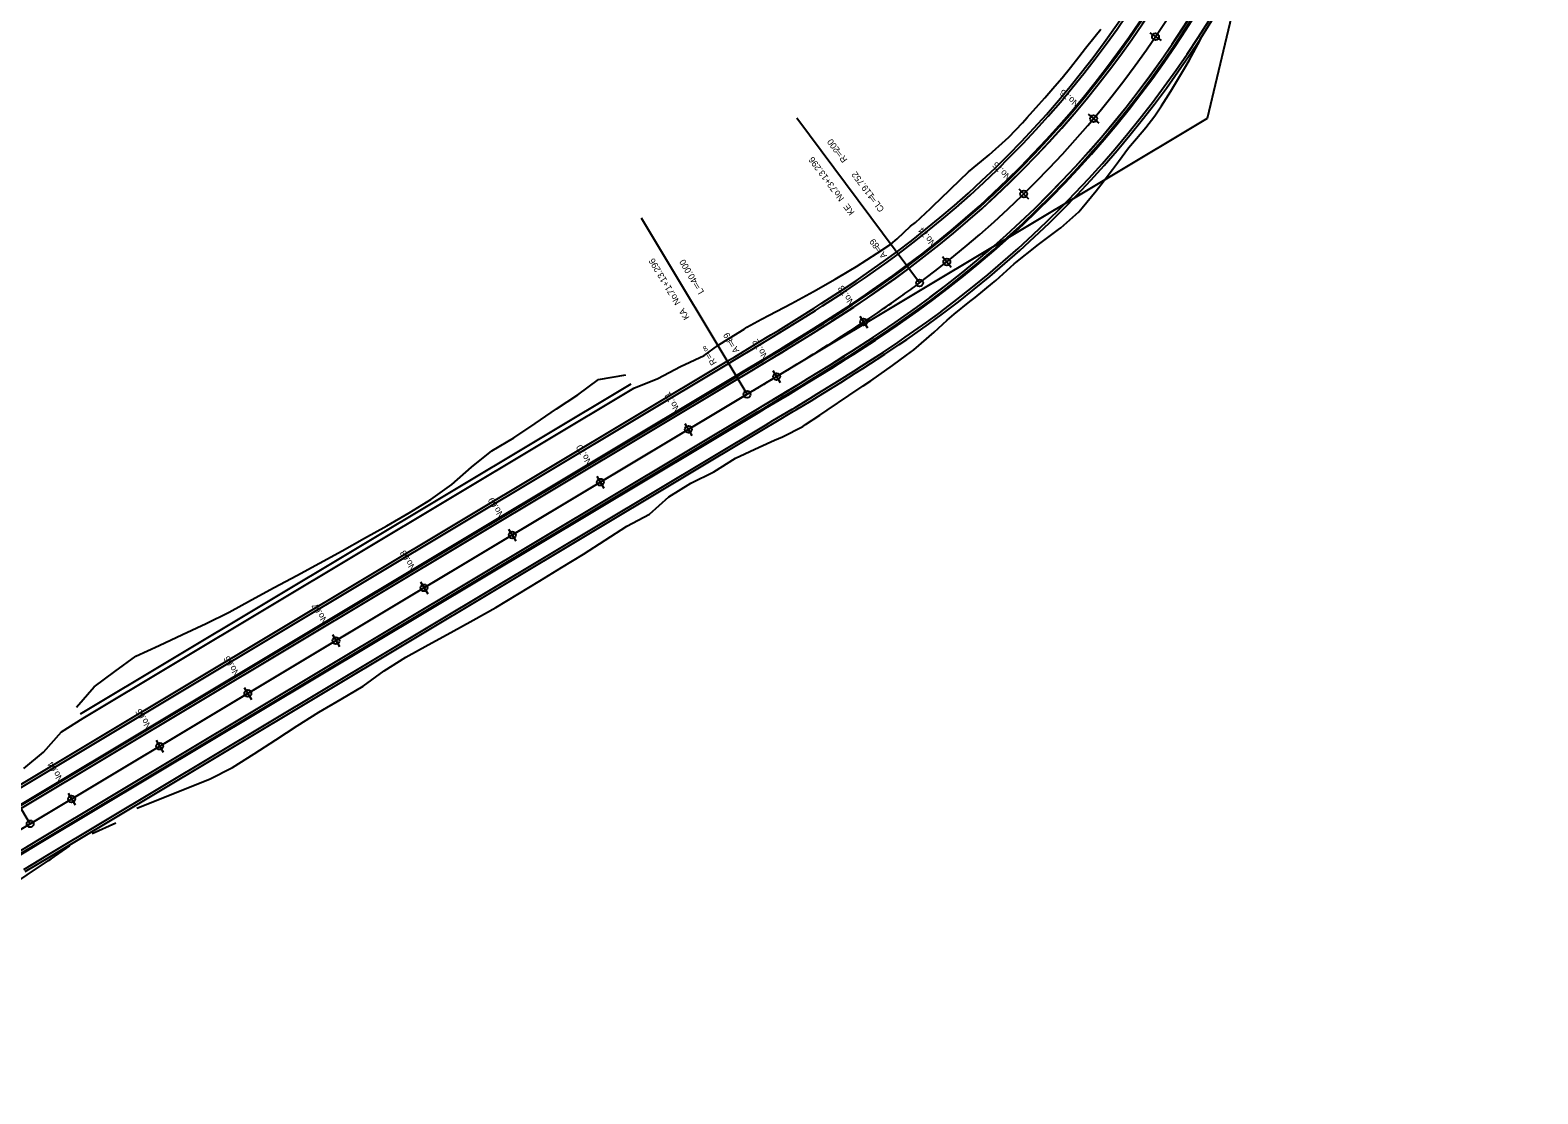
# Model space of a CAD drawing. Extents: x 46424 to 47578, y 10417 to 11548.
# Drawn here: x 47269.9 to 47563.5, y 11080.9 to 11288 of the extents above; entities that cross this region are included whole.
import ezdxf

# ---------------------------------------------------------------- set-up
doc = ezdxf.new("R2010")
doc.units = 0
for name, color, linetype in [('Default', 7, 'Continuous'), ('出典（地理院地図Vector）', 7, 'Continuous'), ('河川_人工水路(地下)（地理院地図Vector）', 7, 'Continuous'), ('現況_地形', 7, 'Continuous'), ('現況_地形_三角形', 7, 'Continuous'), ('現況_地形_三角形_頂点', 7, 'Continuous'), ('現況_地形_低い点', 7, 'Continuous'), ('現況_地形_単点標高', 7, 'Continuous'), ('現況_地形_等高線_マイナー', 7, 'Continuous'), ('等高線等深線_等高線_補助曲線通常部（地理院地図Vector）', 7, 'Continuous'), ('設計図面_測点 ラベル メジャー', 7, 'Continuous'), ('設計図面_測点 印 メジャー', 7, 'Continuous')]:
    doc.layers.add(name, color=color, linetype=linetype)

msp = doc.modelspace()

# ---------------------------------------------------------------- linework, layer by layer
at = {"layer": 'Default'}
for p, q in [((47499.18, 11270.82), (47563.47, 11542.81)), ((47489.04, 11286.7), (47489.04, 11286.7)), ((47182.22, 11080.85), (47499.18, 11270.82)), ((47443.1, 11238.76), (47419.22, 11270.84)), ((47443.1, 11238.76), (47419.22, 11270.84)), ((47476.98, 11270.75), (47476.98, 11270.75)), ((47463.39, 11256.09), (47463.39, 11256.09)), ((47409.51, 11217.07), (47388.95, 11251.38)), ((47448.41, 11242.85), (47448.41, 11242.85)), ((47443.1, 11238.76), (47443.1, 11238.76)), ((47432.21, 11231.14), (47432.21, 11231.14)), ((47415.26, 11220.53), (47415.26, 11220.53)), ((47269.95, 11133.43), (47409.51, 11217.07)), ((47409.51, 11217.07), (47409.51, 11217.07)), ((47398.11, 11210.24), (47398.11, 11210.24)), ((47380.95, 11199.96), (47380.95, 11199.96)), ((47363.8, 11189.68), (47363.8, 11189.68)), ((47346.64, 11179.39), (47346.64, 11179.39)), ((47329.49, 11169.11), (47329.49, 11169.11)), ((47269.95, 11133.43), (47249.39, 11167.74)), ((47312.33, 11158.83), (47312.33, 11158.83)), ((47295.18, 11148.55), (47295.18, 11148.55)), ((47278.02, 11138.27), (47278.02, 11138.27)), ((47269.95, 11133.43), (47269.95, 11133.43))]:
    msp.add_line(p, q, dxfattribs=at)
for centre in [(47489.04, 11286.7), (47476.98, 11270.75), (47463.39, 11256.09), (47448.41, 11242.85), (47443.1, 11238.76), (47432.21, 11231.14), (47415.26, 11220.53), (47409.51, 11217.07), (47398.11, 11210.24), (47380.95, 11199.96), (47363.8, 11189.68), (47346.64, 11179.39), (47329.49, 11169.11), (47312.33, 11158.83), (47295.18, 11148.55), (47278.02, 11138.27), (47269.95, 11133.43)]:
    msp.add_circle(centre, 0.675, dxfattribs=at)
msp.add_arc((47323.67, 11399.19), 200, 306.6653, 340.9717, dxfattribs=at)
msp.add_arc((47323.67, 11399.19), 200, 306.6653, 340.9717, dxfattribs=at)
for points in [[(47409.51, 11217.07), (47410.46, 11217.65), (47412.37, 11218.79), (47416.18, 11221.08), (47420.93, 11223.96), (47426.59, 11227.48), (47432.19, 11231.1), (47436.79, 11234.21), (47440.42, 11236.78), (47442.21, 11238.1), (47443.1, 11238.76)], [(47409.51, 11217.07), (47410.46, 11217.65), (47412.37, 11218.79), (47416.18, 11221.08), (47420.93, 11223.96), (47426.59, 11227.48), (47432.19, 11231.1), (47436.79, 11234.21), (47440.42, 11236.78), (47442.21, 11238.1), (47443.1, 11238.76)], [(47226.71, 11108.33), (47228.54, 11109.32), (47232.19, 11111.33), (47239.46, 11115.42), (47248.47, 11120.63), (47257.44, 11125.94), (47264.59, 11130.22), (47268.16, 11132.36), (47269.95, 11133.43)], [(47226.71, 11108.33), (47228.54, 11109.32), (47232.19, 11111.33), (47239.46, 11115.42), (47248.47, 11120.63), (47257.44, 11125.94), (47264.59, 11130.22), (47268.16, 11132.36), (47269.95, 11133.43)]]:
    msp.add_open_spline(points, degree=3, dxfattribs=at)
at = {"layer": '出典（地理院地図Vector）'}
for points in [[(47266.09, 11139.86), (47405.66, 11223.51), (47407.12, 11224.38), (47410.84, 11226.62), (47411.38, 11226.95), (47414.18, 11228.64), (47415.62, 11229.52), (47419.82, 11232.11), (47422.56, 11233.83), (47423.97, 11234.73), (47428.07, 11237.39), (47430.73, 11239.18), (47432.1, 11240.11), (47436.06, 11242.9), (47438.62, 11244.78)], [(47269.01, 11124.12), (47273.81, 11127), (47413.37, 11210.64), (47414.83, 11211.52), (47418.58, 11213.77), (47419.13, 11214.1), (47421.97, 11215.82), (47423.44, 11216.72), (47427.75, 11219.38), (47430.59, 11221.16), (47432.06, 11222.1), (47436.35, 11224.88), (47439.16, 11226.77), (47440.6, 11227.76), (47444.82, 11230.73), (47447.58, 11232.74)]]:
    msp.add_lwpolyline(points, dxfattribs=at)
for radius in [192.5, 207.5]:
    msp.add_arc((47323.67, 11399.19), radius, 306.6653, 340.9717, dxfattribs=at)
at = {"layer": '河川_人工水路(地下)（地理院地図Vector）'}
msp.add_line((47269.95, 11133.43), (47409.51, 11217.07), dxfattribs=at)
msp.add_arc((47323.67, 11399.19), 200, 306.6653, 340.9717, dxfattribs=at)
for points in [[(47409.51, 11217.07), (47410.46, 11217.65), (47412.37, 11218.79), (47416.18, 11221.08), (47420.93, 11223.96), (47426.59, 11227.48), (47432.19, 11231.1), (47436.79, 11234.21), (47440.42, 11236.78), (47442.21, 11238.1), (47443.1, 11238.76)], [(47226.71, 11108.33), (47228.54, 11109.32), (47232.19, 11111.33), (47239.46, 11115.42), (47248.47, 11120.63), (47257.44, 11125.94), (47264.59, 11130.22), (47268.16, 11132.36), (47269.95, 11133.43)]]:
    msp.add_open_spline(points, degree=3, dxfattribs=at)
at = {"layer": '現況_地形'}
for points in [[(47268.15, 11136.43), (47407.71, 11220.08), (47409.17, 11220.95), (47412.9, 11223.19), (47413.45, 11223.52), (47416.26, 11225.22), (47417.71, 11226.11), (47421.94, 11228.71), (47424.7, 11230.45), (47426.13, 11231.36), (47430.28, 11234.06), (47432.98, 11235.87), (47434.37, 11236.82), (47438.4, 11239.65), (47441.01, 11241.57)], [(47268.15, 11136.44), (47407.71, 11220.08), (47409.17, 11220.96), (47412.9, 11223.2), (47413.44, 11223.53), (47416.25, 11225.23), (47417.7, 11226.11), (47421.93, 11228.72), (47424.7, 11230.46), (47426.12, 11231.37), (47430.27, 11234.07), (47432.97, 11235.88), (47434.36, 11236.83), (47438.39, 11239.66), (47441.01, 11241.57)], [(47266.95, 11127.55), (47271.75, 11130.43), (47411.31, 11214.07), (47412.77, 11214.95), (47416.52, 11217.2), (47417.07, 11217.53), (47419.9, 11219.24), (47421.36, 11220.13), (47425.64, 11222.77), (47428.45, 11224.54), (47429.9, 11225.47), (47434.14, 11228.22), (47436.91, 11230.08), (47438.34, 11231.05), (47442.49, 11233.97), (47445.19, 11235.95)], [(47266.96, 11127.55), (47271.75, 11130.42), (47411.32, 11214.06), (47412.78, 11214.94), (47416.52, 11217.19), (47417.07, 11217.52), (47419.9, 11219.23), (47421.36, 11220.12), (47425.64, 11222.77), (47428.46, 11224.53), (47429.91, 11225.46), (47434.14, 11228.21), (47436.92, 11230.07), (47438.34, 11231.04), (47442.49, 11233.96), (47445.2, 11235.94)]]:
    msp.add_lwpolyline(points, dxfattribs=at)
for radius in [196.5, 196.49, 203.5, 203.51]:
    msp.add_arc((47323.67, 11399.19), radius, 306.6653, 340.9717, dxfattribs=at)
at = {"layer": '現況_地形_三角形'}
msp.add_line((47279.74, 11154.86), (47386.95, 11219.12), dxfattribs=at)
for points in [[(47268.69, 11144.2), (47272.55, 11147.4), (47276.02, 11151.34), (47280.25, 11154), (47387.47, 11218.26), (47392.16, 11220.16), (47396.59, 11222.49), (47401.14, 11224.63), (47403.8, 11226.59), (47405.25, 11227.49), (47408.93, 11229.78), (47409.47, 11230.12), (47412.32, 11231.7), (47413.82, 11232.47), (47418.17, 11234.76), (47421, 11236.29), (47422.46, 11237.09), (47426.68, 11239.49), (47429.43, 11241.11), (47430.83, 11241.96), (47434.88, 11244.53), (47437.5, 11246.28), (47438.72, 11247.36), (47441.33, 11249.81), (47442.29, 11250.53), (47445.21, 11253.23), (47445.77, 11253.77), (47448.92, 11256.84), (47449.18, 11257.08), (47452.6, 11260.36), (47452.65, 11260.4), (47456.26, 11263.39), (47456.63, 11263.71), (47459.82, 11266.55), (47460.49, 11267.17), (47463.14, 11269.95), (47464.03, 11270.94), (47466.31, 11273.49), (47467.48, 11274.79), (47469.46, 11277.06), (47470.86, 11278.72), (47472.49, 11280.72), (47474.09, 11282.76), (47475.43, 11284.45), (47477.32, 11286.81), (47478.39, 11288.19)], [(47290.74, 11136.5), (47295.44, 11138.38), (47300.14, 11140.27), (47304.84, 11142.15), (47309.32, 11144.4), (47313.54, 11147.09), (47317.76, 11149.78), (47321.94, 11152.53), (47326.17, 11155.2), (47330.49, 11157.7), (47334.79, 11160.26), (47338.85, 11163.21), (47343.09, 11165.87), (47347.46, 11168.29), (47351.84, 11170.72), (47356.23, 11173.12), (47360.59, 11175.58), (47364.88, 11178.14), (47369.17, 11180.72), (47373.42, 11183.34), (47377.67, 11185.97), (47381.89, 11188.66), (47386.09, 11191.38), (47390.5, 11193.76), (47394.3, 11197.13), (47398.55, 11199.76), (47403.06, 11201.97), (47407.28, 11204.66), (47411.85, 11206.76), (47414.88, 11208.11), (47416.45, 11208.81), (47420.35, 11210.83), (47420.89, 11211.19), (47423.68, 11213.02), (47425.12, 11213.97), (47429.36, 11216.81), (47432.15, 11218.71), (47433.59, 11219.7), (47437.81, 11222.67), (47440.58, 11224.67), (47441.98, 11225.75), (47445.93, 11229.19), (47448.49, 11231.51), (47449.84, 11232.68), (47452.9, 11235.12), (47453.92, 11235.95), (47457.3, 11238.72), (47457.95, 11239.26), (47461.55, 11242.49), (47461.83, 11242.76), (47465.94, 11245.99), (47466, 11246.04), (47470.17, 11249.14), (47470.6, 11249.47), (47474.12, 11252.62), (47474.77, 11253.39), (47477.46, 11256.68), (47478.37, 11257.83), (47480.67, 11260.83), (47481.82, 11262.39), (47483.8, 11265.04), (47485.34, 11266.86), (47487.14, 11269.05), (47488.88, 11271.31), (47490.22, 11273.27), (47492.01, 11276.07), (47493.01, 11277.7), (47494.93, 11280.95), (47495.65, 11282.2), (47497.68, 11285.91), (47498.14, 11286.78)], [(47278.96, 11156.16), (47282.43, 11160.09), (47286.45, 11163.12), (47290.52, 11166.05), (47295.07, 11168.17), (47299.64, 11170.28), (47304.19, 11172.41), (47308.68, 11174.66), (47313.07, 11177.04), (47317.48, 11179.43), (47321.88, 11181.8), (47326.29, 11184.17), (47330.68, 11186.57), (47335.03, 11189.04), (47339.39, 11191.49), (47343.74, 11193.96), (47347.98, 11196.61), (47352.07, 11199.52), (47355.87, 11202.91), (47359.81, 11206.05), (47364.13, 11208.57), (47368.28, 11211.37), (47372.39, 11214.25), (47376.59, 11216.96), (47380.63, 11219.94), (47385.92, 11220.84)], [(47232.62, 11097.48), (47236.56, 11099.64), (47241, 11102.12), (47243.73, 11103.67), (47245.42, 11104.63), (47248.76, 11108.97), (47252.87, 11111.94), (47253.36, 11112.29), (47256.96, 11114.92), (47261.04, 11117.9), (47263.62, 11119.64), (47265.21, 11120.72), (47269.39, 11123.49), (47273.55, 11126.28), (47274.03, 11126.62), (47277.7, 11129.16)]]:
    msp.add_lwpolyline(points, dxfattribs=at)
at = {"layer": '現況_地形_三角形_頂点'}
msp.add_line((47282.05, 11131.54), (47286.65, 11133.6), dxfattribs=at)
at = {"layer": '現況_地形_低い点'}
for points in [[(47267.89, 11136.86), (47407.45, 11220.5), (47408.91, 11221.38), (47412.64, 11223.62), (47413.19, 11223.95), (47416, 11225.65), (47417.45, 11226.53), (47421.67, 11229.14), (47424.44, 11230.88), (47425.86, 11231.78), (47430, 11234.47), (47432.7, 11236.28), (47434.08, 11237.23), (47438.1, 11240.06), (47440.71, 11241.97)], [(47267.21, 11127.13), (47272.01, 11130), (47411.57, 11213.64), (47413.03, 11214.52), (47416.77, 11216.77), (47417.32, 11217.1), (47420.16, 11218.81), (47421.62, 11219.71), (47425.9, 11222.35), (47428.72, 11224.12), (47430.17, 11225.04), (47434.41, 11227.8), (47437.19, 11229.66), (47438.62, 11230.64), (47442.78, 11233.57), (47445.49, 11235.55)]]:
    msp.add_lwpolyline(points, dxfattribs=at)
for radius in [196, 204]:
    msp.add_arc((47323.67, 11399.19), radius, 306.6653, 340.9717, dxfattribs=at)
at = {"layer": '現況_地形_単点標高'}
for points in [[(47266.35, 11139.43), (47405.91, 11223.08), (47407.37, 11223.95), (47411.1, 11226.19), (47411.64, 11226.52), (47414.44, 11228.21), (47415.88, 11229.09), (47420.09, 11231.68), (47422.83, 11233.41), (47424.24, 11234.31), (47428.34, 11236.98), (47431.02, 11238.77), (47432.38, 11239.7), (47436.35, 11242.49), (47438.92, 11244.37)], [(47267.79, 11137.03), (47407.35, 11220.68), (47408.81, 11221.55), (47412.54, 11223.79), (47413.09, 11224.12), (47415.9, 11225.82), (47417.34, 11226.7), (47421.57, 11229.31), (47424.33, 11231.05), (47425.75, 11231.95), (47429.89, 11234.64), (47432.59, 11236.45), (47433.97, 11237.39), (47437.99, 11240.22), (47440.59, 11242.13)], [(47267.31, 11126.95), (47272.11, 11129.83), (47411.67, 11213.47), (47413.13, 11214.35), (47416.88, 11216.6), (47417.43, 11216.93), (47420.26, 11218.64), (47421.72, 11219.54), (47426.01, 11222.18), (47428.83, 11223.95), (47430.28, 11224.88), (47434.52, 11227.64), (47437.3, 11229.5), (47438.73, 11230.47), (47442.9, 11233.4), (47445.61, 11235.39)], [(47268.75, 11124.55), (47273.55, 11127.43), (47413.11, 11211.07), (47414.57, 11211.95), (47418.32, 11214.2), (47418.87, 11214.53), (47421.71, 11216.25), (47423.18, 11217.15), (47427.49, 11219.8), (47430.33, 11221.59), (47431.79, 11222.52), (47436.07, 11225.3), (47438.88, 11227.18), (47440.32, 11228.17), (47444.53, 11231.13), (47447.28, 11233.14)]]:
    msp.add_lwpolyline(points, dxfattribs=at)
for radius in [193, 195.8, 204.2, 207]:
    msp.add_arc((47323.67, 11399.19), radius, 306.6653, 340.9717, dxfattribs=at)
at = {"layer": '現況_地形_等高線_マイナー'}
for points in [[(47267.88, 11136.88), (47407.44, 11220.52), (47408.9, 11221.4), (47412.63, 11223.64), (47413.18, 11223.97), (47415.99, 11225.67), (47417.44, 11226.55), (47421.66, 11229.16), (47424.43, 11230.89), (47425.85, 11231.8), (47429.99, 11234.49), (47432.69, 11236.3), (47434.07, 11237.25), (47438.09, 11240.07), (47440.7, 11241.98)], [(47267.22, 11127.11), (47272.02, 11129.98), (47411.58, 11213.63), (47413.04, 11214.5), (47416.78, 11216.75), (47417.33, 11217.08), (47420.17, 11218.8), (47421.63, 11219.69), (47425.91, 11222.33), (47428.73, 11224.1), (47430.18, 11225.03), (47434.43, 11227.79), (47437.2, 11229.65), (47438.63, 11230.62), (47442.79, 11233.55), (47445.5, 11235.53)]]:
    msp.add_lwpolyline(points, dxfattribs=at)
for radius in [195.98, 204.02]:
    msp.add_arc((47323.67, 11399.19), radius, 306.6653, 340.9717, dxfattribs=at)
at = {"layer": '等高線等深線_等高線_補助曲線通常部（地理院地図Vector）'}
msp.add_line((47269.95, 11133.43), (47409.51, 11217.07), dxfattribs=at)
msp.add_arc((47323.67, 11399.19), 200, 306.6653, 340.9717, dxfattribs=at)
for points in [[(47409.51, 11217.07), (47410.46, 11217.65), (47412.37, 11218.79), (47416.18, 11221.08), (47420.93, 11223.96), (47426.59, 11227.48), (47432.19, 11231.1), (47436.79, 11234.21), (47440.42, 11236.78), (47442.21, 11238.1), (47443.1, 11238.76)], [(47226.71, 11108.33), (47228.54, 11109.32), (47232.19, 11111.33), (47239.46, 11115.42), (47248.47, 11120.63), (47257.44, 11125.94), (47264.59, 11130.22), (47268.16, 11132.36), (47269.95, 11133.43)]]:
    msp.add_open_spline(points, degree=3, dxfattribs=at)
at = {"layer": '設計図面_測点 印 メジャー'}
for p, q in [((47487.92, 11287.46), (47490.16, 11285.94)), ((47475.95, 11271.62), (47478.02, 11269.88)), ((47462.45, 11257.05), (47464.34, 11255.12)), ((47447.57, 11243.91), (47449.25, 11241.8)), ((47431.46, 11232.26), (47432.95, 11230.01)), ((47414.56, 11221.68), (47415.95, 11219.37)), ((47397.41, 11211.4), (47398.8, 11209.08)), ((47380.26, 11201.11), (47381.64, 11198.8)), ((47363.1, 11190.83), (47364.49, 11188.52)), ((47345.95, 11180.55), (47347.34, 11178.24)), ((47328.79, 11170.27), (47330.18, 11167.95)), ((47311.64, 11159.99), (47313.03, 11157.67)), ((47294.48, 11149.71), (47295.87, 11147.39)), ((47277.33, 11139.43), (47278.72, 11137.11))]:
    msp.add_line(p, q, dxfattribs=at)

# ---------------------------------------------------------------- texts
at = {"layer": 'Default'}
for s, rotation, p in [('200', 126.6653, (47427.67, 11264.71)), ('73+13.296', 126.6653, (47427.13, 11257.08)), ('R＝', 126.6653, (47429.13, 11262.76)), ('119.752', 126.6653, (47434.37, 11255.73)), ('\u3000No.', 126.6653, (47429.55, 11253.82)), ('KE', 126.6653, (47430.52, 11252.52)), ('CL＝', 126.6653, (47436.31, 11253.12)), ('89', 126.6653, (47435.35, 11246.02)), ('A＝', 126.6653, (47436.81, 11244.07)), ('71+13.296', 120.9357, (47395.45, 11236.89)), ('40.000', 120.9357, (47399.95, 11239.11)), ('\u3000No.', 120.9357, (47397.53, 11233.41)), ('L＝', 120.9357, (47401.2, 11237.02)), ('KA', 120.9357, (47398.37, 11232.02)), ('89', 120.9357, (47406.82, 11227.65)), ('A＝', 120.9357, (47408.07, 11225.56)), ('R＝∞', 120.9357, (47403.66, 11223.19))]:
    msp.add_text(s, height=1.25, rotation=rotation, dxfattribs=at).set_placement(p)
at = {"layer": '設計図面_測点 ラベル メジャー'}
for s, rotation, p in [('76', 140.0449, (47472.45, 11275.36)), ('No.', 140.0449, (47474.32, 11273.8)), ('75', 134.3153, (47459.35, 11261.13)), ('No.', 134.3153, (47461.05, 11259.38)), ('74', 128.5858, (47444.88, 11248.27)), ('No.', 128.5858, (47446.4, 11246.37)), ('73', 123.4893, (47429.18, 11236.85)), ('No.', 123.4893, (47430.52, 11234.82)), ('72', 121.0967, (47412.47, 11226.36)), ('No.', 121.0967, (47413.73, 11224.27)), ('71', 120.9357, (47395.33, 11216.08)), ('No.', 120.9357, (47396.59, 11213.99)), ('70', 120.9357, (47378.18, 11205.8)), ('No.', 120.9357, (47379.43, 11203.71)), ('69', 120.9357, (47361.02, 11195.52)), ('No.', 120.9357, (47362.28, 11193.43)), ('68', 120.9357, (47343.87, 11185.24)), ('No.', 120.9357, (47345.12, 11183.15)), ('67', 120.9357, (47326.71, 11174.95)), ('No.', 120.9357, (47327.97, 11172.86)), ('66', 120.9357, (47309.56, 11164.67)), ('No.', 120.9357, (47310.81, 11162.58)), ('65', 120.9357, (47292.4, 11154.39)), ('No.', 120.9357, (47293.66, 11152.3)), ('64', 120.9357, (47275.25, 11144.11)), ('No.', 120.9357, (47276.5, 11142.02))]:
    msp.add_text(s, height=1.25, rotation=rotation, dxfattribs=at).set_placement(p)

doc.saveas('drawing.dxf')
